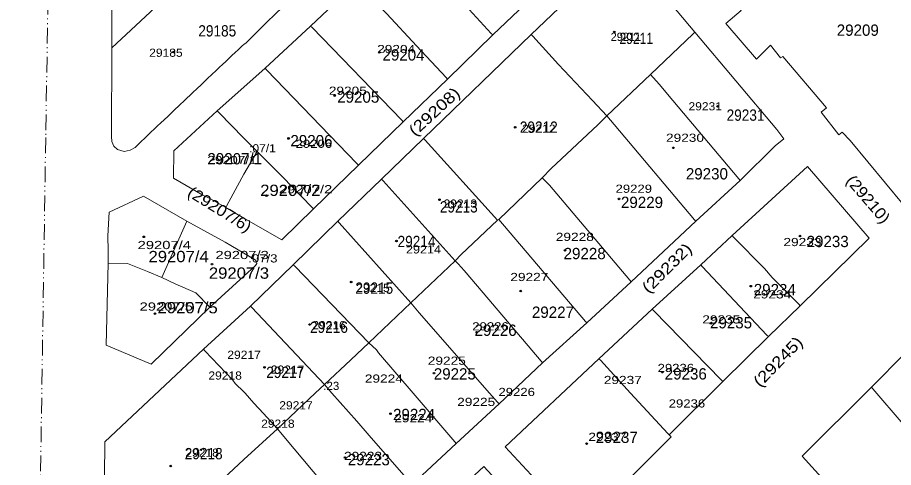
# Model space of a CAD drawing. Extents: x 650553 to 652508, y 239277 to 241647.
# Drawn here: x 650553 to 650831.5, y 239726.3 to 239869.5 of the extents above; entities that cross this region are included whole.
import ezdxf

# ---------------------------------------------------------------- set-up
doc = ezdxf.new("R2010")
doc.units = 0
doc.header["$PDMODE"] = 32
doc.header["$PDSIZE"] = 0.5
doc.linetypes.add('DASH_DOUBLE_DOT', pattern=[9.2, 5, -1.2, 0.3, -1.2, 0.3, -1.2])
for name, color, linetype in [('19', 7, 'Continuous'), ('20', 7, 'Continuous'), ('6', 7, 'Continuous')]:
    doc.layers.add(name, color=color, linetype=linetype)
for name, color, linetype, lineweight in [('3', 7, 'Continuous', 13), ('5', 7, 'Continuous', 13), ('52', 7, 'DASH_DOUBLE_DOT', 13)]:
    doc.layers.add(name, color=color, linetype=linetype, lineweight=lineweight)

msp = doc.modelspace()

# ---------------------------------------------------------------- linework, layer by layer
at = {"layer": '3'}
for p, q in [((650632.64, 239868.3), (650631.44, 239867.13)), ((650630.7, 239866.41), (650629.42, 239865.16)), ((650631.44, 239867.13), (650630.7, 239866.41)), ((650626.86, 239862.65), (650625.67, 239861.5)), ((650627.56, 239863.34), (650626.86, 239862.65)), ((650628.7, 239864.45), (650627.56, 239863.34)), ((650629.42, 239865.16), (650628.7, 239864.45)), ((650624.44, 239860.49), (650625, 239860.95)), ((650625.67, 239861.5), (650625, 239860.95)), ((650620.35, 239856.61), (650621.17, 239857.38)), ((650621.17, 239857.38), (650622.21, 239858.37)), ((650617.13, 239853.56), (650618.25, 239854.62)), ((650618.25, 239854.62), (650619.08, 239855.41)), ((650619.08, 239855.41), (650620.35, 239856.61)), ((650614.82, 239851.37), (650616.13, 239852.61)), ((650616.13, 239852.61), (650617.13, 239853.56)), ((650611.29, 239848.03), (650613.42, 239850.05)), ((650613.42, 239850.05), (650614.82, 239851.37)), ((650608.67, 239845.55), (650610.19, 239846.98)), ((650610.19, 239846.98), (650611.29, 239848.03)), ((650605.89, 239842.91), (650606.83, 239843.8)), ((650606.83, 239843.8), (650607.88, 239844.79)), ((650607.88, 239844.79), (650608.67, 239845.55)), ((650602.62, 239839.81), (650604.74, 239841.82)), ((650604.74, 239841.82), (650605.89, 239842.91)), ((650599.58, 239836.93), (650600.87, 239838.15)), ((650600.87, 239838.15), (650601.53, 239838.77)), ((650601.53, 239838.77), (650602.62, 239839.81)), ((650596.42, 239833.93), (650597.43, 239834.89)), ((650597.43, 239834.89), (650598.59, 239835.99)), ((650598.59, 239835.99), (650599.58, 239836.93)), ((650593.47, 239831.14), (650594.35, 239831.98)), ((650594.35, 239831.98), (650595.53, 239833.1)), ((650595.53, 239833.1), (650596.42, 239833.93)), ((650591.35, 239829.14), (650592.37, 239830.1)), ((650592.37, 239830.1), (650593.47, 239831.14)), ((650581.76, 239800.07), (650581.78, 239795.26)), ((650628.69, 239790.61), (650625, 239787.24)), ((650802.53, 239729.93), (650824.49, 239751.82))]:
    msp.add_line(p, q, dxfattribs=at)
for points in [[(650746.57, 240000), (650755.43, 239988.73), (650755.33, 239986.98), (650744.89, 239977.09), (650733.47, 239966.21), (650731.38, 239963.86), (650724.78, 239957.6), (650722.46, 239955.48), (650711.31, 239944.45), (650698.75, 239932.17), (650688.83, 239922.64), (650672.51, 239906.75), (650654.73, 239889.78), (650634.64, 239870.25), (650632.64, 239868.3)], [(650762.84, 239977.13), (650748.77, 239963.83), (650733.41, 239949.35), (650719.05, 239935.4), (650704.44, 239921.94), (650689.85, 239908.09), (650675.57, 239894.28), (650660.72, 239880.56), (650646.18, 239866.8), (650631.73, 239853.39)], [(650625, 239933.84), (650619.55, 239928.48), (650605.85, 239914.63), (650605.55, 239914.81), (650582.94, 239892.73), (650582.97, 239859.88), (650582.91, 239831.62), (650582.97, 239830.06), (650583.67, 239828.56), (650584.81, 239827.53), (650586.87, 239826.85), (650588.87, 239827.33), (650590.42, 239828.19), (650591.35, 239829.14)], [(650636.99, 239798.79), (650647.09, 239808.65), (650661.42, 239822.51), (650675.67, 239836.3), (650689.76, 239849.94), (650704.11, 239863.97), (650718.5, 239877.81), (650732.86, 239891.63), (650747.4, 239905.68), (650761.67, 239919.63), (650775.13, 239932.91)], [(650758.53, 239902.67), (650760.73, 239900.19), (650759.19, 239898.72), (650765.32, 239891.73), (650766.99, 239892.99), (650780.49, 239876.39), (650779.94, 239875.79), (650783.12, 239871.78), (650778.188, 239867.604), (650787.995, 239856.292), (650792.37, 239860.72), (650795.54, 239856.63), (650796.29, 239857.11), (650810.17, 239840.72), (650808.48, 239839.35), (650814.17, 239832.2), (650815.19, 239833.07), (650817.72, 239830.34), (650834.635, 239810.007), (650871.916, 239846.694)], [(650580.38, 239689.62), (650580.75, 239734.46), (650612.1, 239763.93), (650627.06, 239777.69), (650640.68, 239790.82), (650654.82, 239804.68), (650668.76, 239818.06), (650682.12, 239830.96), (650716.35, 239864.08), (650745.15, 239891.65)], [(650745.15, 239891.65), (650745.93, 239891.69), (650768.36, 239864.8)], [(650768.36, 239864.8), (650794.405, 239833.862), (650796.608, 239830.924), (650793.863, 239828.628), (650782.78, 239817.68), (650768.67, 239804.67), (650748.15, 239785.39), (650733.99, 239772.3), (650719.95, 239759.65), (650706.09, 239746.56), (650692.5, 239733.96), (650678.47, 239720.85), (650662.83, 239706.18), (650648.6, 239693.12), (650634.81, 239680.2), (650631.87, 239677.45)], [(650622.21, 239858.37), (650623.12, 239859.24), (650624.44, 239860.49)], [(650631.73, 239853.39), (650625, 239847.36), (650616.51, 239839.76)], [(650616.51, 239839.76), (650602.71, 239827.08), (650602.55, 239818.35), (650611.93, 239812.95), (650614.1, 239811.87), (650619.2, 239809)], [(650760.22, 239736.65), (650760.87, 239736.09), (650731.71, 239706.88), (650725.59, 239713.35), (650725.99, 239713.6), (650708.05, 239732.82), (650737.88, 239760.92), (650754.83, 239776.64), (650770.26, 239790.78), (650780.2, 239800.09), (650804.13, 239822.14)], [(650804.13, 239822.14), (650823.81, 239799.29), (650801.89, 239777.77), (650791.74, 239767.94), (650777.21, 239753.64), (650760.22, 239736.65)], [(650619.04, 239798.01), (650606.89, 239804.7), (650593.09, 239812.68), (650582.18, 239807.53), (650581.76, 239800.07)], [(650619.2, 239809), (650625, 239805.67), (650636.99, 239798.79)], [(650625, 239794.48), (650620.88, 239796.92), (650619.04, 239798.01)], [(650581.78, 239795.26), (650581.79, 239791.37), (650581.19, 239765.24), (650595.46, 239759.16), (650614.16, 239777.3), (650625, 239787.24)], [(650625, 239794.48), (650628.59, 239792.36), (650628.95, 239791.83), (650629.07, 239791.27), (650628.69, 239790.61)], [(650824.49, 239751.82), (650845.96, 239773.46), (650851.58, 239767.89), (650851.19, 239767.43), (650865.28, 239751.04), (650879.32, 239734.62), (650858.42, 239712.84)], [(650858.42, 239712.84), (650837.68, 239691.06), (650802.53, 239729.93)], [(650679.85, 239656.67), (650660.338, 239678.861), (650659.846, 239678.207), (650654.69, 239683.89), (650659.02, 239688.01), (650659.31, 239687.67), (650677.97, 239704.96), (650701.302, 239726.619), (650724.616, 239701.337)]]:
    msp.add_lwpolyline(points, dxfattribs=at)
at = {"layer": '5'}
for p, q in [((650625, 239819.68), (650629.24, 239826.88)), ((650719.85, 239818.48), (650722.1, 239816.2)), ((650625, 239750.38), (650625.39, 239750))]:
    msp.add_line(p, q, dxfattribs=at)
for points in [[(650615.84, 239890.53), (650615.51, 239890.27), (650613.85, 239888.66), (650610.42, 239885.49), (650601.32, 239877.1), (650582.97, 239859.88)], [(650660.72, 239880.56), (650661.212, 239880.06), (650670.47, 239870.65), (650679.84, 239860.47)], [(650694.28, 239874.58), (650703.647, 239864.47), (650704.11, 239863.97)], [(650646.18, 239866.8), (650646.663, 239866.3), (650675.187, 239836.8), (650675.67, 239836.3)], [(650768.36, 239864.8), (650767.86, 239864.325), (650754.28, 239851.42), (650740.36, 239838.18), (650737.47, 239835.38), (650722.68, 239821.5), (650719.85, 239818.48), (650706.04, 239805.24), (650705.59, 239805.05), (650694.09, 239794.08), (650692.12, 239792.11), (650678.094, 239778.663), (650678.08, 239778.65), (650664.74, 239765.95), (650658.98, 239760.54), (650650.58, 239752.76), (650647.67, 239750)], [(650716.35, 239864.08), (650716.807, 239863.58), (650725.02, 239854.6), (650735.85, 239843.13), (650740.36, 239838.18), (650742.68, 239835.49)], [(650679.84, 239860.47), (650689.289, 239850.44), (650689.76, 239849.94)], [(650631.73, 239853.39), (650632.211, 239852.89), (650660.939, 239823.01), (650661.42, 239822.51)], [(650754.28, 239851.42), (650757.01, 239848.29), (650761.41, 239843.15)], [(650761.41, 239843.15), (650782.36, 239818.18), (650782.78, 239817.68)], [(650616.51, 239839.76), (650617.002, 239839.26), (650625, 239831.14)], [(650742.68, 239835.49), (650768.248, 239805.17), (650768.67, 239804.67)], [(650625, 239831.14), (650626.27, 239829.85), (650629.24, 239826.88), (650637.25, 239818.84)], [(650682.12, 239830.96), (650682.573, 239830.46), (650705.59, 239805.05)], [(650619.2, 239809), (650619.469, 239809.5), (650624.32, 239818.52), (650625, 239819.68)], [(650637.25, 239818.84), (650646.607, 239809.15), (650647.09, 239808.65)], [(650668.76, 239818.06), (650669.21, 239817.56), (650692.12, 239792.11), (650693.06, 239791.16), (650695.04, 239788.98), (650701.1, 239781.88)], [(650722.1, 239816.2), (650747.727, 239785.89), (650748.15, 239785.39)], [(650606.89, 239804.7), (650604.26, 239798.99), (650598.91, 239786.76)], [(650654.82, 239804.68), (650655.267, 239804.18), (650678.02, 239778.75), (650678.094, 239778.663), (650680.75, 239775.56), (650703.08, 239750)], [(650706.04, 239805.24), (650733.566, 239772.8), (650733.99, 239772.3)], [(650780.2, 239800.09), (650780.69, 239799.59), (650790.47, 239789.6), (650792.98, 239786.78)], [(650581.79, 239791.37), (650588, 239791.25), (650594.3, 239788.63), (650598.91, 239786.76), (650603.14, 239784.71), (650609.69, 239781.89), (650614.16, 239777.3)], [(650640.68, 239790.82), (650641.164, 239790.32), (650664.74, 239765.95), (650667.1, 239763.72), (650667.76, 239762.82), (650678.75, 239750)], [(650770.26, 239790.78), (650770.73, 239790.28), (650791.27, 239768.44), (650791.74, 239767.94)], [(650792.98, 239786.78), (650801.396, 239778.27), (650801.89, 239777.77)], [(650701.1, 239781.88), (650719.526, 239760.15), (650719.95, 239759.65)], [(650627.06, 239777.69), (650627.532, 239777.19), (650650.58, 239752.76), (650652.99, 239750)], [(650754.83, 239776.64), (650755.317, 239776.14), (650776.723, 239754.14), (650777.21, 239753.64)], [(650612.1, 239763.93), (650612.575, 239763.43), (650621.46, 239754.07), (650622.25, 239753.05), (650625, 239750.38)], [(650737.88, 239760.92), (650738.341, 239760.42), (650747.94, 239750)], [(650844.2, 239728.86), (650824.919, 239751.32), (650824.49, 239751.82)], [(650647.67, 239750), (650635.71, 239738.65), (650625, 239728.79)], [(650625.39, 239750), (650628.13, 239746.8), (650631.23, 239743.46), (650635.71, 239738.65), (650637.65, 239736.16)], [(650652.99, 239750), (650660.86, 239741), (650664.79, 239736.5)], [(650678.75, 239750), (650692.071, 239734.46), (650692.5, 239733.96)], [(650703.08, 239750), (650705.653, 239747.06), (650706.09, 239746.56)], [(650760.22, 239736.65), (650759.76, 239737.15), (650747.94, 239750)], [(650637.65, 239736.16), (650662.41, 239706.68), (650662.83, 239706.18)], [(650664.79, 239736.5), (650678.033, 239721.35), (650678.47, 239720.85)], [(650580.38, 239689.62), (650580.88, 239689.614), (650586.4, 239689.55), (650586.41, 239693.04), (650608.13, 239713.16), (650621.7, 239725.75), (650625, 239728.79)]]:
    msp.add_lwpolyline(points, dxfattribs=at)
at = {"layer": '52'}
msp.add_lwpolyline([(650605.404, 240765.589), (650575.102, 240622.376), (650564.111, 240019.547), (650563.292, 239912.239), (650561.967, 239831.306), (650558.948, 239635.138), (650557.76, 239590.469), (650555.824, 239499.761), (650555.114, 239481.758), (650553.994, 239393.396), (650554.019, 239393.395), (650553.222, 239318.763), (650553.006, 239301.006), (650586.911, 239277.281)], dxfattribs=at)
at = {"layer": '6'}
for p in [(650742.745, 239864.935), (650602.688, 239858.56), (650668.017, 239858.43), (650653.86, 239844.655), (650775.603, 239841.24), (650711.224, 239834.565), (650639.178, 239831.02), (650761.521, 239828.045), (650615.214, 239824.38), (650632.156, 239812.835), (650687.175, 239811.535), (650744.251, 239811.785), (650593.179, 239799.72), (650673.483, 239798.361), (650801.785, 239799.955), (650727.046, 239795.39), (650614.84, 239791), (650659.076, 239785.315), (650713, 239782.445), (650786.168, 239784.015), (650596.741, 239775.265), (650645.858, 239771.79), (650773.433, 239772.21), (650698.963, 239769.335), (650631.522, 239758.17), (650758.052, 239756.645), (650685.453, 239756.311), (650671.584, 239743.4), (650733.94, 239733.9), (650657.102, 239729.47), (650601.73, 239726.74)]:
    msp.add_point(p, dxfattribs=at)

# ---------------------------------------------------------------- texts
at = {"layer": '19'}
for s, width, p in [('29185', 0.9, (650610.492, 239863.469)), ('29211', 0.8, (650744.378, 239861.075)), ('29231', 0.9, (650778.451, 239836.653)), ('29212', 0.9, (650712.707, 239832.822)), ('29207/2', 1.1, (650630.159, 239812.709)), ('29213', 0.9, (650687.274, 239807.442)), ('29214', 0.9, (650673.836, 239796.429)), ('29207/4', 1.1, (650594.649, 239791.639)), ('29207/3', 1.1, (650613.844, 239786.372)), ('29215', 0.9, (650660.401, 239781.584)), ('29207/5', 1.1, (650597.528, 239775.358)), ('29216', 0.9, (650646.004, 239769.134)), ('29217', 0.9, (650632.088, 239754.768)), ('29218', 0.9, (650606.175, 239728.909))]:
    msp.add_text(s, height=3.6, dxfattribs=dict(at, width=width)).set_placement(p)
for s, p in [('29209', (650813.472, 239863.691)), ('29204', (650669.036, 239855.807)), ('29205', (650654.641, 239842.399)), ('29206', (650639.766, 239828.512)), ('29207/1', (650613.365, 239822.765)), ('29230', (650765.494, 239817.977)), ('29229', (650744.859, 239808.879)), ('29233', (650803.885, 239796.429)), ('29228', (650726.624, 239792.598)), ('29234', (650787.088, 239781.105)), ('29227', (650716.547, 239773.922)), ('29235', (650773.173, 239770.57)), ('29226', (650698.312, 239768.176)), ('29225', (650685.355, 239754.289)), ('29236', (650758.777, 239754.289)), ('29224', (650672.397, 239741.36)), ('29237', (650736.837, 239734.099)), ('29223', (650658.002, 239726.994))]:
    msp.add_text(s, height=3.6, dxfattribs=at).set_placement(p)
for s, rotation, width, p in [('(29208)', 42.62, 1.2, (650679.402, 239831.518)), ('(29210)', 310.691, 1.1, (650816.149, 239817.428)), ('(29207/6)', 328.256, 1.1, (650606.714, 239812.914)), ('(29232)', 44.91, 1.2, (650753.671, 239781.471)), ('(29245)', 45.741, 1.2, (650789.126, 239751.59))]:
    msp.add_text(s, height=3.6, rotation=rotation, dxfattribs=dict(at, width=width)).set_placement(p)
at = {"layer": '20'}
msp.add_text('29211', height=2.6, dxfattribs=at).set_placement((650741.593, 239862.074))
for s, width, p in [('29204', 1.25, (650667.357, 239858.18)), ('29185', 1.1, (650594.873, 239857.005)), ('29205', 1.25, (650651.988, 239844.912)), ('29231', 1.1, (650766.337, 239839.954)), ('29212', 1.1, (650713.429, 239832.819)), ('29230', 1.25, (650759.183, 239829.943)), (':07/1', 1.1, (650626.627, 239826.6)), ('29206', 1.2, (650641.428, 239828.021)), ('29207/1', 1.25, (650613.352, 239822.861)), ('29207/2', 1.35, (650636.114, 239813.567)), ('29229', 1.2, (650743.139, 239813.719)), ('29213', 1.1, (650688.463, 239808.994)), ('29207/4', 1.35, (650591.188, 239795.808)), ('29228', 1.25, (650724.148, 239798.403)), ('29233', 1.25, (650796.526, 239796.757)), ('29214', 1.15, (650676.52, 239794.41)), ('29207/3', 1.35, (650615.936, 239792.629)), (':07/3', 1.2, (650626.377, 239791.55)), ('29227', 1.25, (650709.691, 239785.631)), ('29215', 1.1, (650660.711, 239782.155)), ('29234', 1.25, (650786.914, 239780.102)), ('29207/5', 1.35, (650591.81, 239776.223)), ('29235', 1.25, (650770.721, 239772.126)), ('29216', 1.1, (650646.732, 239770.303)), ('29226', 1.2, (650697.59, 239769.925)), ('29217', 1.1, (650619.719, 239760.874)), ('29225', 1.25, (650683.452, 239758.99)), ('29218', 1.1, (650613.696, 239754.261)), ('29217', 1.1, (650633.542, 239756.15)), ('29236', 1.2, (650756.519, 239756.679)), ('29224', 1.25, (650663.439, 239753.294)), ('29237', 1.25, (650739.414, 239752.848)), (':23', 1.05, (650650.232, 239750.972)), ('29226', 1.2, (650705.912, 239749.035)), ('29225', 1.25, (650692.799, 239745.88)), ('29217', 1.1, (650636.236, 239744.786)), ('29236', 1.2, (650760.039, 239745.373)), ('29224', 1.25, (650672.793, 239740.684)), ('29218', 1.1, (650630.472, 239738.944)), ('29237', 1.25, (650734.499, 239734.746)), ('29218', 1.1, (650606.382, 239729.713)), ('29223', 1.25, (650656.832, 239728.681))]:
    msp.add_text(s, height=2.6, dxfattribs=dict(at, width=width)).set_placement(p)

doc.saveas('drawing.dxf')
